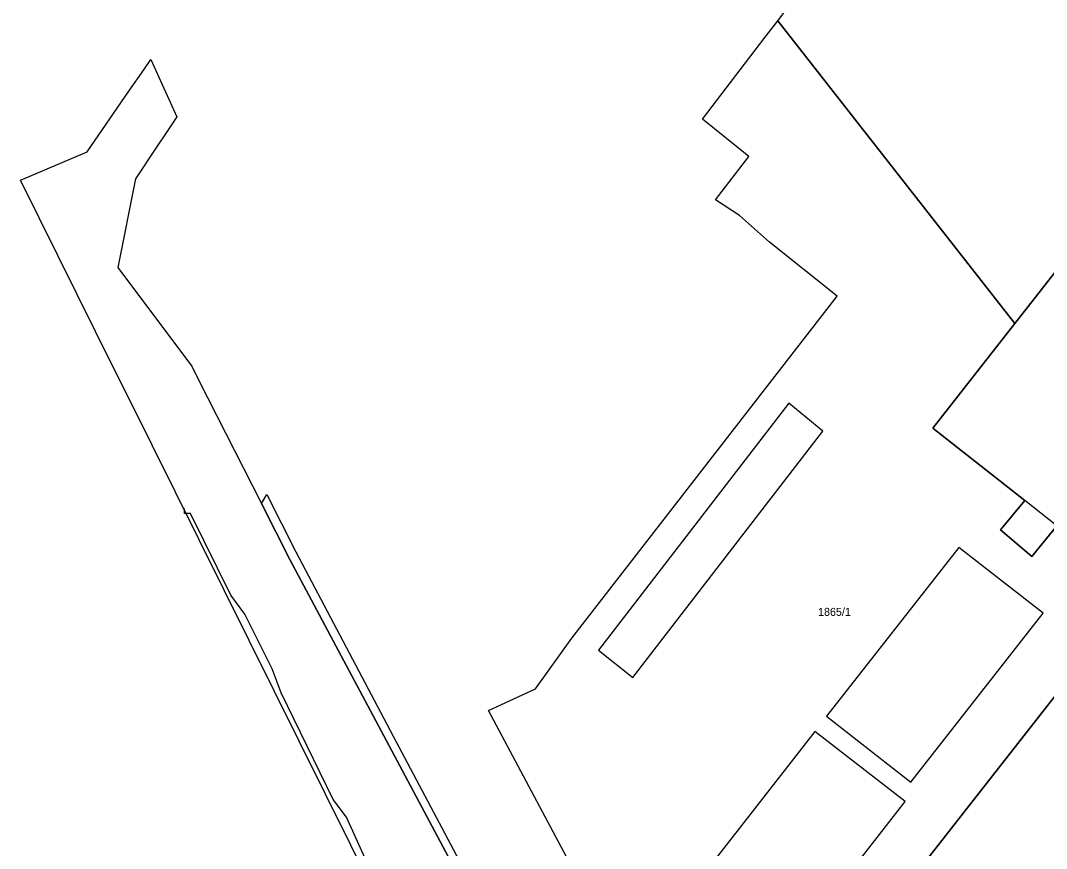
# Model space of a CAD drawing. Extents: x -793400 to -756198, y -1074141 to -1042963.
# Drawn here: x -783768.8 to -783672.6, y -1065017.1 to -1064939.5 of the extents above; entities that cross this region are included whole.
import ezdxf

# ---------------------------------------------------------------- set-up
doc = ezdxf.new("R2010")
doc.units = 0
for name, color, linetype in [('Parcela', 7, 'Continuous'), ('Popiskový text - Parcela', 7, 'Continuous'), ('Stavební objekt', 7, 'Continuous'), ('Vedení nn kabelové', 7, 'Continuous')]:
    doc.layers.add(name, color=color, linetype=linetype)

msp = doc.modelspace()

# ---------------------------------------------------------------- linework, layer by layer
at = {"layer": 'Parcela'}
for points in [[(-783684.31, -1064921.88), (-783672.83, -1064935.41), (-783664.71, -1064928.55), (-783661.86, -1064931.6), (-783668.19, -1064937.03), (-783657.46, -1064949.13), (-783656.26, -1064948.06), (-783645.86, -1064959.82), (-783641.09, -1064955.5), (-783634.11, -1064963.54), (-783657.73, -1064987.44), (-783659.12, -1064988.88), (-783663.52, -1064983.25), (-783650.04, -1064966.03), (-783664.98, -1064954.39), (-783675.55, -1064967.88), (-783697.77, -1064939.49), (-783696.58, -1064937.94)], [(-783663.52, -1064983.25), (-783668.33, -1064989.39), (-783671.6, -1064986.83), (-783673.96, -1064989.72), (-783676.88, -1064987.22), (-783674.61, -1064984.45), (-783683.24, -1064977.69), (-783675.55, -1064967.88), (-783664.98, -1064954.39), (-783650.04, -1064966.03)], [(-783693.56, -1064977.95), (-783696.74, -1064975.34), (-783714.59, -1064998.5), (-783711.36, -1065001.05)], [(-783679.72, -1065068.87), (-783696.3, -1065082.59), (-783703.49, -1065067.95), (-783701.82, -1065066.6), (-783693.07, -1065059.53), (-783681.16, -1065034.03), (-783688.84, -1065024.56), (-783667.93, -1064997.88), (-783659.12, -1064988.88), (-783657.73, -1064987.44), (-783656.18, -1064989.41), (-783657.28, -1064990.53), (-783648.71, -1064998.93), (-783633.99, -1065017.67), (-783634.29, -1065017.9), (-783683.34, -1065055.48), (-783678.2, -1065062.3), (-783682.41, -1065065.47)], [(-783672.88, -1064995.01), (-783680.81, -1064988.86), (-783693.2, -1065004.69), (-783685.29, -1065010.87)], [(-783685.82, -1065012.69), (-783694.29, -1065006.1), (-783713.7, -1065030.98), (-783705.23, -1065037.6)]]:
    msp.add_lwpolyline(points, close=True, dxfattribs=at)
for points in [[(-783715.02, -1065022.66), (-783724.9, -1065004.13), (-783720.48, -1065002.12), (-783717.08, -1064997.37), (-783692.21, -1064965.3), (-783698.55, -1064960.25), (-783701.37, -1064957.75), (-783703.6, -1064956.27), (-783700.48, -1064952.2), (-783704.84, -1064948.71), (-783699.07, -1064941.19), (-783697.77, -1064939.49), (-783675.55, -1064967.88), (-783683.24, -1064977.69), (-783674.61, -1064984.45), (-783676.88, -1064987.22), (-783673.96, -1064989.72), (-783671.6, -1064986.83)], [(-783728.08, -1065036.33), (-783742.64, -1065007.02), (-783752.01, -1064988.16), (-783758.63, -1064974.82), (-783759.96, -1064972.14), (-783768.75, -1064954.44), (-783762.5, -1064951.77), (-783758.59, -1064946.1), (-783757.2, -1064944.08), (-783756.54, -1064943.13), (-783754.1, -1064948.5), (-783754.84, -1064949.61), (-783756.19, -1064951.63), (-783757.98, -1064954.32), (-783759.63, -1064962.62), (-783757.88, -1064964.96), (-783752.7, -1064971.88), (-783752.06, -1064973.15), (-783746.17, -1064984.74), (-783743.49, -1064990.04), (-783721.39, -1065031.49)], [(-783721.39, -1065031.49), (-783743.49, -1064990.04), (-783746.17, -1064984.74), (-783745.67, -1064983.89), (-783742.95, -1064989.28), (-783733.81, -1065006.54), (-783721.18, -1065030.38)], [(-783667.93, -1064997.88), (-783688.84, -1065024.56)]]:
    msp.add_lwpolyline(points, dxfattribs=at)
at = {"layer": 'Stavební objekt'}
msp.add_lwpolyline([(-783663.52, -1064983.25), (-783668.33, -1064989.39), (-783671.6, -1064986.83), (-783674.61, -1064984.45), (-783683.24, -1064977.69), (-783675.55, -1064967.88), (-783664.98, -1064954.39), (-783650.04, -1064966.03)], close=True, dxfattribs=at)
at = {"layer": 'Vedení nn kabelové'}
msp.add_lwpolyline([(-783735.73, -1065019.607), (-783738.183, -1065014.143), (-783739.451, -1065012.496), (-783744.324, -1065002.489), (-783745.174, -1065000.23), (-783747.731, -1064995.124), (-783749.042, -1064993.334), (-783752.81, -1064985.671), (-783752.942, -1064985.671), (-783753.394, -1064985.671), (-783753.394, -1064985.203)], dxfattribs=at)

# ---------------------------------------------------------------- texts
at = {"layer": 'Popiskový text - Parcela'}
msp.add_text('1865/1', height=0.75, dxfattribs=at).set_placement((-783693.992, -1064995.275))

doc.saveas('drawing.dxf')
